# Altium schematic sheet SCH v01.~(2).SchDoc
size A3; SheetNumber: 1; SheetTotal: 1
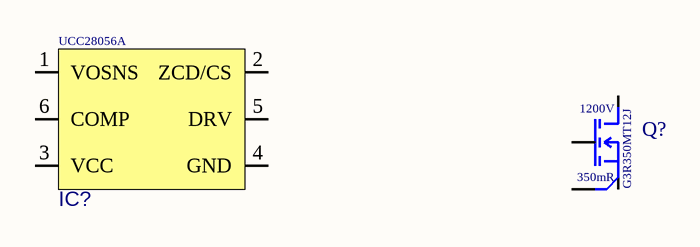
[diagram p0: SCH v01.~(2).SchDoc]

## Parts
IC?  UCC28056A  [SOT-23-6]
Q?  Manufacturer Part Number: G3R350MT12J  Rds: 350mR  Voltage: 1200V  [TO-263-7 D2PAK]  (hidden comment: Nmos_KS)

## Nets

Not connected (* = marked no-connect by the designer): IC? 1(VOSNS) 2(ZCD/CS) 3(VCC) 4(GND) 5(DRV) 6(COMP); Q? D G KS S

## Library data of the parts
IC? = UCC28056A: PFC TM IC; Manufacturer: Texas Instruments
Q? = Nmos_KS: Generic Nmos symbol with Kelvin Source; Manufacturer: GeneSiC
